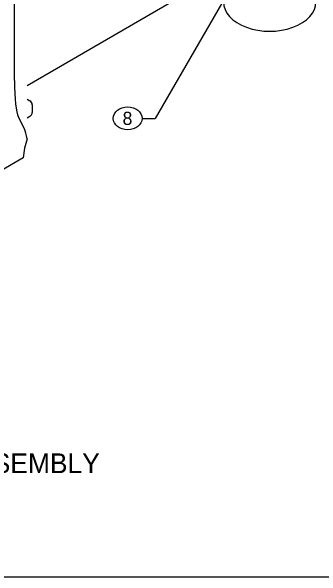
# Model space of a CAD drawing. Extents: x 99862 to 103151, y 100000 to 105076.
# Drawn here: x 101811 to 102188, y 100000 to 100686 of the extents above; entities that cross this region are included whole.
import ezdxf

# ---------------------------------------------------------------- set-up
doc = ezdxf.new("R2010")
doc.units = 0
for name, color, linetype in [('Level 1', 7, 'Continuous'), ('Level 15', 7, 'Continuous'), ('Level 16', 7, 'Continuous'), ('Level 20', 7, 'Continuous'), ('Level 31', 7, 'Continuous'), ('Level 33', 7, 'Continuous')]:
    doc.layers.add(name, color=color, linetype=linetype)

msp = doc.modelspace()

# ---------------------------------------------------------------- linework, layer by layer
at = {"layer": 'Level 1'}
msp.add_lwpolyline([(99862, 99999.5), (103151, 99999.5), (103151, 102075.5), (99862, 102075.5)], close=True, dxfattribs=at)
at = {"layer": 'Level 15'}
for p in [(102086.78, 100731.43), (101969.75, 100556.43)]:
    msp.add_line(p, (101985.75, 100556.43), dxfattribs=at)
at = {"layer": 'Level 16'}
msp.add_line((102092.56, 100748.42), (101829.96, 100595.75), dxfattribs=at)
at = {"layer": 'Level 20'}
msp.add_ellipse((101952.25, 100556.43), major_axis=(-17.5, 0), ratio=0.8, dxfattribs=at)
at = {"layer": 'Level 31'}
msp.add_ellipse((102124.95, 100697.99), major_axis=(56.25, 0), ratio=0.635085, start_param=3.14158, end_param=6.283185, dxfattribs=at)
at = {"layer": 'Level 33'}
for p, q in [((101814.71, 100602.51), (101814.71, 100951.57)), ((101829.98, 100579.73), (101833.43, 100577.74)), ((101836.24, 100572.87), (101836.24, 100563.68)), ((101826.83, 100543.59), (101819.59, 100557.82)), ((101833.43, 100558.81), (101829.98, 100556.82)), ((101825.15, 100508.33), (101753.56, 100466.99))]:
    msp.add_line(p, q, dxfattribs=at)
for centre, start, end in [((101830.62, 100572.87), 0, 60), ((101830.62, 100563.68), 300, 0)]:
    msp.add_arc(centre, 5.63, start, end, dxfattribs=at)
for centre, major_axis, ratio, start_param, end_param in [((101849.87, 100751.41), (-26.97, -196.72), 0.114691, 5.586537, 6.119546), ((101796.55, 100350), (-26.97, -196.72), 0.114691, 2.760167, 2.977954), ((101935.86, 100430.43), (-78.75, 136.4), 0.57735, 0.470176, 0.676453)]:
    msp.add_ellipse(centre, major_axis=major_axis, ratio=ratio, start_param=start_param, end_param=end_param, dxfattribs=at)

# ---------------------------------------------------------------- texts
at = {"layer": 'Level 20'}
for s, height, p in [('8', 16, (101946.1, 100548.43)), ('ACCESSIBLE PEDESTRIAN SIGNAL (ASP) ASSEMBLY', 24, (101099.78, 100125.35))]:
    msp.add_text(s, height=height, dxfattribs=at).set_placement(p)

doc.saveas('drawing.dxf')
